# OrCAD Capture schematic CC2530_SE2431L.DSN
size Custom; title: CC2530-SE2431L; rev: 1.4
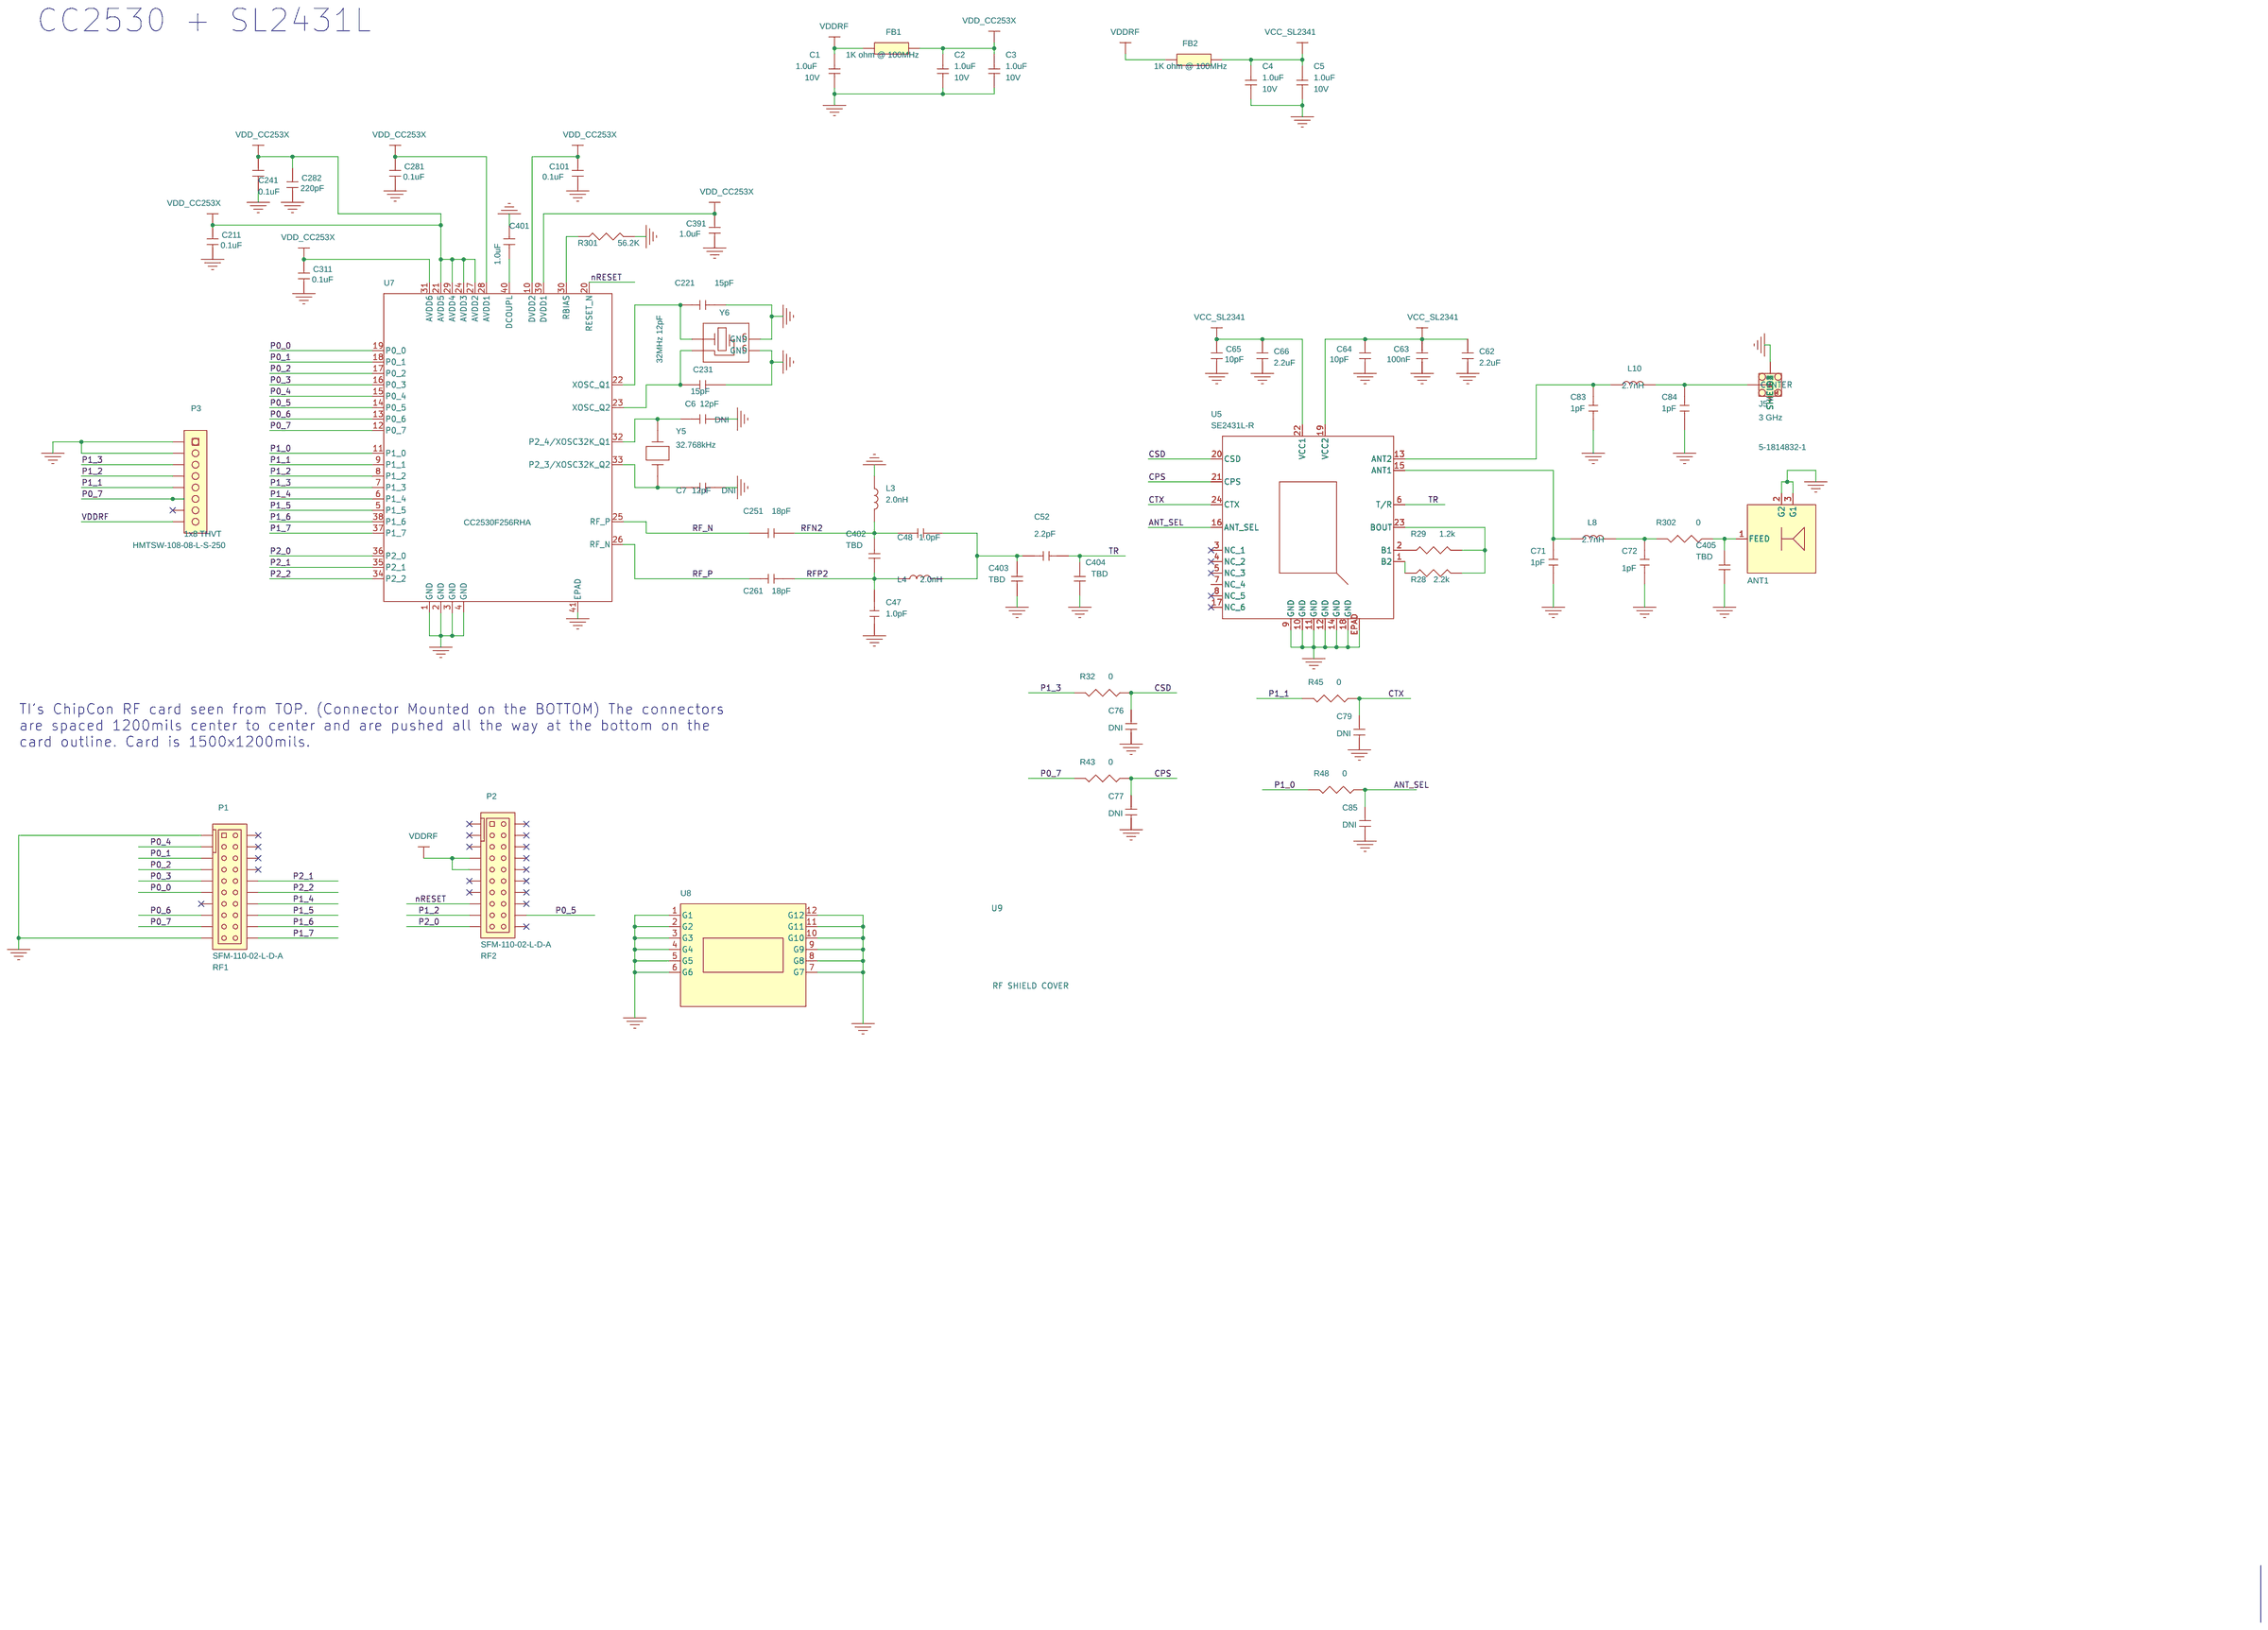
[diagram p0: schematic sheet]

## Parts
ANT1  N/A  [ANT_IIFA_CC2420_62mil]
C1  1.0uF  [0402]
C2  1.0uF  [0402]
C3  1.0uF  [0402]
C4  1.0uF  [0402]
C5  1.0uF  [0402]
C6  12pF  [0402]
C7  12pF  [0402]
C47  1.0pF  [0402]
C48  1.0pF  [0402]
C52  2.2pF  [0402]
C62  2.2uF  [0402]
C63  100nF  [0402]
C64  10pF  [0402]
C65  10pF  [0402]
C66  2.2uF  [0402]
C71  1.8pF  [0402]
C72  1.8pF  [0402]
C76  DNI  [0402]
C77  DNI  [0402]
C79  DNI  [0402]
C83  1.8pF  [0402]
C84  1.8pF  [0402]
C85  DNI  [0402]
C101  0.1uF  [0402]
C211  0.1uF  [0402]
C221  15pF  [0402]
C231  15pF  [0402]
C241  0.1uF  [0402]
C251  18pF  [0402]
C261  18pF  [0402]
C281  0.1uF  [0402]
C282  220pF  [0402]
C311  0.1uF  [0402]
C391  1.0uF  [0402]
C401  1.0uF  [0402]
C402  TBD  [0402]
C403  TBD  [0402]
C404  TBD  [0402]
C405  TBD  [0402]
FB1  1K ohm @ 100MHz  [FB_0402]
FB2  1K ohm @ 100MHz  [FB_0402]
J5  3 GHz  [SMA_THVT_5-1814832-1]
L3  2.0nH  [0402]
L4  2.0nH  [0402]
L8  1.2nH  [0402]
L10  1.2nH  [0402]
P1  SFM-110-02-L-D-A  [CON_SMVT_2x10_50_F_SFM_FLIP_CC]
P2  SFM-110-02-L-D-A  [CON_SMVT_2x10_50_F_SFM_FLIP_CC]
P3  1x8 THVT  [HDR_THVT_1x8_100_M]
R28  2.2k  [0402]
R29  1.2k  [0402]
R32  0  [0402]
R43  0  [0402]
R45  0  [0402]
R48  0  [0402]
R301  56.2K  [0402]
R302  0  [0402]
U5  SE2431L-R  [QFN_24_EP1p70x2p70]
U7  CC2530F256RHA  [PVQFN_RHA40_EP4p50SQ]
U8  RF SHIELD  [SH_BMI-S-209_1p156x728]
U9  RF SHIELD COVER
Y5  32.768kHz  [XTAL_130x63x36]
Y6  32MHz 12pF  [XTAL_4_SM_83x67x20]

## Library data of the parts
ANT1 = ANT_IIFA_CC2420_62mil
C1-C5 = CAP_NP: ALT_SYMBOLS: 0402_SMALL; Link2Local Datasheet: C:\PCB_LIBRARY\CADENCE\DATASHEETS\mlcc03_e.pdf; Link2MFG Datasheet: http://search.digikey.com/scripts/DkSearch/dksus.dll?Detail&name=587-1454-2-ND; Manufacturer: Taiyo Yuden; Manufacturer Part Number: LMK105BJ105KV-F; Part Description: CAP CER 1.0UF 10V X5R 0402; TEMP °C: -55 to 125; Voltage: 10V
C6 C7 = CAP_NP_v2: Manufacturer: Taiyo Yuden; Manufacturer Part Number: EMK042CG120JC-F; Note: DNI; TOL: 5%; VOLTAGE: 16V
C47 C48 = CAP_NP_v2: Manufacturer: Murata; Manufacturer Part Number: GRM1555C1H1R0CZ01D; TOL: NPO +/-0.25pF; VOLTAGE: 50V
C52 = CAP_NP_v2: Manufacturer: Murata; Manufacturer Part Number: GRM1555C1H2R2CZ01D; TOL: NPO +/-0.25pF; VOLTAGE: 50V
C62 C66 = CAP0402: Manufacturer: Taiyo Yuden; Manufacturer Part Number: JMK105BJ225MV-F
C63-C65 C76 C77 C79 C85 C101 C211 C241 C281 C311 = CAP0402: Manufacturer: Taiyo Yuden; Manufacturer Part Number: LMK105BJ104KV-F
C71 C72 C83 C84 = CAP_NP_v2: Manufacturer: Murata; Manufacturer Part Number: GRM1555C1H1R8CZ01D; Note: 1pF; TOL: NPO +/-0.25pF; VOLTAGE: 50V
C221 C231 = CAP_NP_v2: Manufacturer: Murata; Manufacturer Part Number: GRM1555C1H150JZ01D; TOL: +/-5%; VOLTAGE: 50V
C251 C261 = CAP_NP_v2: Manufacturer: Murata; Manufacturer Part Number: GRM1555C1H180JZ01D; TOL: +/-5%; VOLTAGE: 50V
C282 = CAP0402: Manufacturer: Taiyo Yuden; Manufacturer Part Number: UMK105B7221KV-F
C391 C401 = CAP0402: Manufacturer: Taiyo Yuden; Manufacturer Part Number: LMK105BJ105KV-F
C402-C405 = CAP_NP: Link2Local Datasheet: N/A; Link2MFG Datasheet: N/A; Manufacturer: N/A; Manufacturer Part Number: N/A; Part Description: Blank capacitor 0402 - PADS only in the layout
FB1 FB2 = FERRITE_BEAD: Link2Local Datasheet: C:\PCB_LIBRARY\CADENCE\DATASHEETS\mlci07_e.pdf; Link2MFG Datasheet: http://www.yuden.co.jp/us/product/pdf/mlci07_e.pdf; Manufacturer: Taiyo Yuden; Manufacturer Part Number: BK1005HS102-T; Part Description: FERRITE BEAD 1000OHM 0402
J5 = SMA_5P: Link2MFG Datasheet: http://search.digikey.com/us/en/products/5-1814832-1/A97594-ND/1755982; Manufacturer: TE Connectivity; Manufacturer Part Number: 5-1814832-1; Part Description: CONN SOCKET SMA STR DIE CAST PCB
L3 L4 = IND0402: Manufacturer: Murata; Manufacturer Part Number: LQW15AN2N0J00D; Note: No alternative
L8 L10 = IND0402: Manufacturer: Murata; Manufacturer Part Number: LQW15AN1N2J00D; Note: 2.7nH
P1 = CON_SMVT_2x10_50_F_SFM_FLIP_CC: Link2Local Datasheet: C:\PCB_LIBRARY\CADENCE\DATASHEETS\SFM_Series; Manufacturer: Samtec; Manufacturer Part Number: SFM-110-02-S-D-A; Note: REFER TO ASSEMBLY DRAWING FOR PIN 1 LOCATION; TI_SILKTEXT: RF1
P2 = CON_SMVT_2x10_50_F_SFM_FLIP_CC: Link2Local Datasheet: C:\PCB_LIBRARY\CADENCE\DATASHEETS\SFM_Series; Manufacturer: Samtec; Manufacturer Part Number: SFM-110-02-S-D-A; Note: REFER TO ASSEMBLY DRAWING FOR PIN 1 LOCATION; TI_SILKTEXT: RF2
P3 = HEADER_1x8: Manufacturer: Samtec; Manufacturer Part Number: HMTSW-108-08-L-S-250; Part Description: Header_1x8_100_THVT_M_530L
R28 R29 = RES0402: Manufacturer: Panasonic-ECG; Manufacturer Part Number: ERJ-2GEJ681X; Mfr_Part_Number: ERJ-2GEJ681X; TOL: 5%
R32 R43 R45 R48 R302 = RES0402: Manufacturer: Panasonic-ECG; Manufacturer Part Number: ERJ-2GE0R101X; Mfr_Part_Number: ERJ-2GE0R101X; TOL: 5%
R301 = RES0402: Manufacturer: Panasonic-ECG; Manufacturer Part Number: ERJ-2RKF5622X; Mfr_Part_Number: ERJ-2RKF5622X; TOL: 1%
U5 = SE2431L_QFN24: Link2MFG Datasheet: http://www.skyworksinc.com/uploads/documents/SE2431L_DS.pdf; Manufacturer: Skyworks Solutions Inc; Part Description: IC RF FRONT END MOD 2.4GHZ 24QFN; Watt: 2.4GHz
U7 = CC2530Fxx_RHA40: Link2MFG Datasheet: http://focus.ti.com/lit/ds/symlink/cc2533.pdf; Manufacturer: Texas Instruments; Part Description: IC SOC IEEE 802.15.4/ZIG 40-QFN 256K Flash; TEMP °C: -40 to 125; Voltage: 2 to 3.6V; Watt: 2.4GHz
U8 = RF_SHIELD_12P: Link2Local Datasheet: C:\PCB_LIBRARY\CADENCE\DATASHEETS\EMI_Board_Level_Shields_and_Contacts.pdf; Link2MFG Datasheet: http://in.mouser.com/search/ProductDetail.aspx?qs=RzyoSnN9rS0izmILg9YGPw%3d%3d&amp;cm_mmc=findchips-_-na-_-na-_-na; Manufacturer: Laird Technologies EMI; Manufacturer Part Number: BMI-S-209-F; Note: Include cover BMI-S-209-C; Part Description: BOARD SHIELD 1.156X0.728" FRAME
U9 = RF_SHIELD_COVER: Link2Local Datasheet: C:\PCB_LIBRARY\CADENCE\DATASHEETS\EMI_Board_Level_Shields_and_Contacts.pdf; Link2MFG Datasheet: http://in.mouser.com/search/ProductDetail.aspx?qs=RzyoSnN9rS3tVnkK5tkfNw%3d%3d&amp;cm_mmc=findchips-_-na-_-na-_-na; Manufacturer: Laird Technologies EMI; Manufacturer Part Number: BMI-S-209-C; Part Description: BOARD SHIELD 1.156X0.728" COVER
Y5 = XTAL_32p768kHz_CC7V_T1A: Manufacturer: Micro Crystal
Y6 = XTAL_4_FA-128_32MHz_10ppm_12pF

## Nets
GND: ANT1.2(G2) ANT1.3(G1) C1.2 C2.2 C3.2 C4.2 C5.2 C6.2 C7.2 C47.1 C62.2 C63.2 C64.2 C65.2 C66.2 C71.1 C72.1 C76.2 C77.2 C79.2 C83.1 C84.1 C85.2 C101.2 C211.2 C221.2 C231.2 C241.2 C281.2 C282.2 C311.2 C391.2 C401.1 C403.2 C404.2 C405.2 J5.2(SHIELD1) J5.3(SHIELD2) J5.4(SHIELD4) J5.5(SHIELD3) L3.2 P1.1 P1.19 P3.1 P3.2 R301.2 U5.9(GND) U5.10(GND) U5.11(GND) U5.12(GND) U5.14(GND) U5.18(GND) U5.EPAD U7.1(GND) U7.2(GND) U7.3(GND) U7.4(GND) U7.41(EPAD) U8.1(G1) U8.2(G2) U8.3(G3) U8.4(G4) U8.5(G5) U8.6(G6) U8.7(G7) U8.8(G8) U8.9(G9) U8.10(G10) U8.11(G11) U8.12(G12) Y6.2(GND) Y6.4(GND)
VCC_SL2341: C4.1 C5.1 C62.1 C63.1 C64.1 C65.1 C66.1 FB2.2 U5.19(VCC2) U5.22(VCC1)
VDD_CC253x: C2.1 C3.1 C101.1 C211.1 C241.1 C281.1 C282.1 C311.1 C391.1 FB1.2 U7.10(DVDD2) U7.21(AVDD5) U7.24(AVDD3) U7.27(AVDD2) U7.28(AVDD1) U7.29(AVDD4) U7.31(AVDD6) U7.39(DVDD1)
VDDRF: C1.1 FB1.1 FB2.1 P2.7 P2.9 P3.8
ANT_SEL: C85.1 R48.2 U5.16(ANT_SEL)
CPS: C77.1 R43.2 U5.21(CPS)
CSD: C76.1 R32.2 U5.20(CSD)
CTX: C79.1 R45.2 U5.24(CTX)
NC_4: U5.7(NC_4)
nRESET: P2.15 U7.20(RESET_N)
P0_0: P1.11 U7.19(P0_0)
P0_1: P1.5 U7.18(P0_1)
P0_2: P1.7 U7.17(P0_2)
P0_3: P1.9 U7.16(P0_3)
P0_4: P1.3 U7.15(P0_4)
P0_5: P2.18 U7.14(P0_5)
P0_6: P1.15 U7.13(P0_6)
P0_7: P1.17 P3.6 R43.1 U7.12(P0_7)
P1_0: R48.1 U7.11(P1_0)
P1_1: P3.5 R45.1 U7.9(P1_1)
P1_2: P2.17 P3.4 U7.8(P1_2)
P1_3: P3.3 R32.1 U7.7(P1_3)
P1_4: P1.14 U7.6(P1_4)
P1_5: P1.16 U7.5(P1)
P1_6: P1.18 U7.38(P1_6)
P1_7: P1.20 U7.37(P1_7)
P2_0: P2.19 U7.36(P2_0)
P2_1: P1.10 U7.35(P2_1)
P2_2: P1.12 U7.34(P2_2)
RF_N: C251.1 U7.25(RF_P)
RF_P: C261.1 U7.26(RF_N)
RFN2: C48.2 C251.2 C402.1 L3.1
RFP2: C47.2 C261.2 C402.2 L4.2
TR: C52.1 C404.1 U5.6(T/R)
N15887617: R301.1 U7.30(RBIAS)
N15888121: C48.1 C52.2 C403.1 L4.1
N15888255: C231.1 U7.23(XOSC_Q2) Y6.3
N15888299: C221.1 U7.22(XOSC_Q1) Y6.1
N15888951: C7.1 U7.33(P2_3/XOSC32K_Q2) Y5.1
N15888993: C6.1 U7.32(P2_4/XOSC32K_Q1) Y5.2
N15927937: R28.1 R29.1 U5.23(BOUT)
N15931758: R28.2 U5.1(B2)
N15960596: C71.2 L8.2 U5.15(ANT1)
N15960606: C72.2 L8.1 R302.1
N15963823: R29.2 U5.2(B1)
N15982649: C83.2 L10.2 U5.13(ANT2)
N15984570: C84.2 J5.1(CENTER) L10.1
N15998457: C401.2 U7.40(DCOUPL)
N16008692: ANT1.1(FEED) C405.1 R302.2

Not connected (* = marked no-connect by the designer): P1 2* 4* 6* 8* 13*; P2 1* 2* 3* 4* 5* 6* 8* 10* 11* 12* 13* 14* 16* 20*; P3 7*; U5 3(NC_1)* 4(NC_2)* 5(NC_3)* 8(NC_5)* 17(NC_6)*

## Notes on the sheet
- CC2530 + SL2431L
- TI's ChipCon RF card seen from TOP. (Connector Mounted on the BOTTOM) The connectors
  are spaced 1200mils center to center and are pushed all the way at the bottom on the
  card outline. Card is 1500x1200mils.
